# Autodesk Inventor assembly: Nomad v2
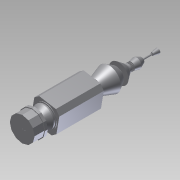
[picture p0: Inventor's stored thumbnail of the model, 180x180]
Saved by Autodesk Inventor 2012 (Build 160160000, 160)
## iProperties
Created: 2012-10
Part Number: Nomad v2
Document SubType Name: Assembly
Designer: TechShop Member
Author: TechShop Member
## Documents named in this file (15)
- E:\Inventor 2012\Nomad\With Hole\Nomad v2.iam
- E:\Inventor 2012\Nomad\With Hole\NomadPart3.ipt
- E:\Inventor 2012\Nomad\With Hole\NomadPart4.ipt
- E:\Inventor 2012\Nomad\With Hole\NomadPart5.ipt
- E:\Inventor 2012\Nomad\With Hole\NomadParts6and7.ipt
- E:\Inventor 2012\Nomad\With Hole\NomadPart8.ipt
- E:\Inventor 2012\Nomad\With Hole\NomadPart9.ipt
- E:\Inventor 2012\Nomad\With Hole\NomadPart10.ipt
- E:\Inventor 2012\Nomad\With Hole\NomadParts12to15.ipt
- E:\Inventor 2012\Nomad\With Hole\NomadPart16.ipt
- E:\Inventor 2012\Nomad\With Hole\NomadParts17and18.ipt
- E:\Inventor 2012\Nomad\With Hole\NomadParts19to23.ipt
- E:\Inventor 2012\Nomad\With Hole\NomadPart24.ipt
- E:\Inventor 2012\Nomad\With Hole\NomadPart1.ipt
- E:\Inventor 2012\Nomad\With Hole\NomadPart2.ipt
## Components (14 placed, 14 different names)
1. NomadPart1:1 — Mate:28, Mate:29, Mate:30
2. NomadPart2:1 — Mate:28, Mate:29, Mate:30, Mate:31, Mate:32
3. NomadPart3:1 — Mate:6, Mate:7, Mate:31, Mate:32
4. NomadPart4:1 — Mate:6, Mate:7, Mate:8, Mate:9
5. NomadPart5:1 — Mate:8, Mate:9, Mate:10, Mate:11
6. NomadParts6and7:1 — Mate:10, Mate:11, Mate:12, Mate:13
7. NomadPart8:1 — Mate:12, Mate:13, Mate:14, Mate:15
8. NomadPart9:1 — Mate:14, Mate:15, Mate:16, Mate:17
9. NomadPart10:1 — Mate:16, Mate:17, Mate:18, Mate:19
10. NomadParts12to15:1 — Mate:18, Mate:19, Mate:20, Mate:21
11. NomadPart16:1 — Mate:20, Mate:21, Mate:22, Mate:23
12. NomadParts17and18:1 — Mate:22, Mate:23, Mate:24, Mate:25
13. NomadParts19to23:1 — Mate:24, Mate:25, Mate:26, Mate:27
14. NomadPart24:1 — Mate:26, Mate:27
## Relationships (27: Mate 27)
- Mate:6: NomadPart3:1 ↔ NomadPart4:1
- Mate:7: NomadPart3:1 ↔ NomadPart4:1
- Mate:8: NomadPart4:1 ↔ NomadPart5:1
- Mate:9: NomadPart4:1 ↔ NomadPart5:1
- Mate:10: NomadPart5:1 ↔ NomadParts6and7:1
- Mate:11: NomadPart5:1 ↔ NomadParts6and7:1
- Mate:12: NomadParts6and7:1 ↔ NomadPart8:1
- Mate:13: NomadParts6and7:1 ↔ NomadPart8:1
- Mate:14: NomadPart8:1 ↔ NomadPart9:1
- Mate:15: NomadPart8:1 ↔ NomadPart9:1
- Mate:16: NomadPart9:1 ↔ NomadPart10:1
- Mate:17: NomadPart9:1 ↔ NomadPart10:1
- Mate:18: NomadPart10:1 ↔ NomadParts12to15:1
- Mate:19: NomadPart10:1 ↔ NomadParts12to15:1
- Mate:20: NomadParts12to15:1 ↔ NomadPart16:1
- Mate:21: NomadParts12to15:1 ↔ NomadPart16:1
- Mate:22: NomadPart16:1 ↔ NomadParts17and18:1
- Mate:23: NomadPart16:1 ↔ NomadParts17and18:1
- Mate:24: NomadParts17and18:1 ↔ NomadParts19to23:1
- Mate:25: NomadParts17and18:1 ↔ NomadParts19to23:1
- Mate:26: NomadParts19to23:1 ↔ NomadPart24:1
- Mate:27: NomadParts19to23:1 ↔ NomadPart24:1
- Mate:28: NomadPart1:1 ↔ NomadPart2:1
- Mate:29: NomadPart1:1 ↔ NomadPart2:1
- Mate:30: NomadPart1:1 ↔ NomadPart2:1
- Mate:31: NomadPart2:1 ↔ NomadPart3:1
- Mate:32: NomadPart2:1 ↔ NomadPart3:1
